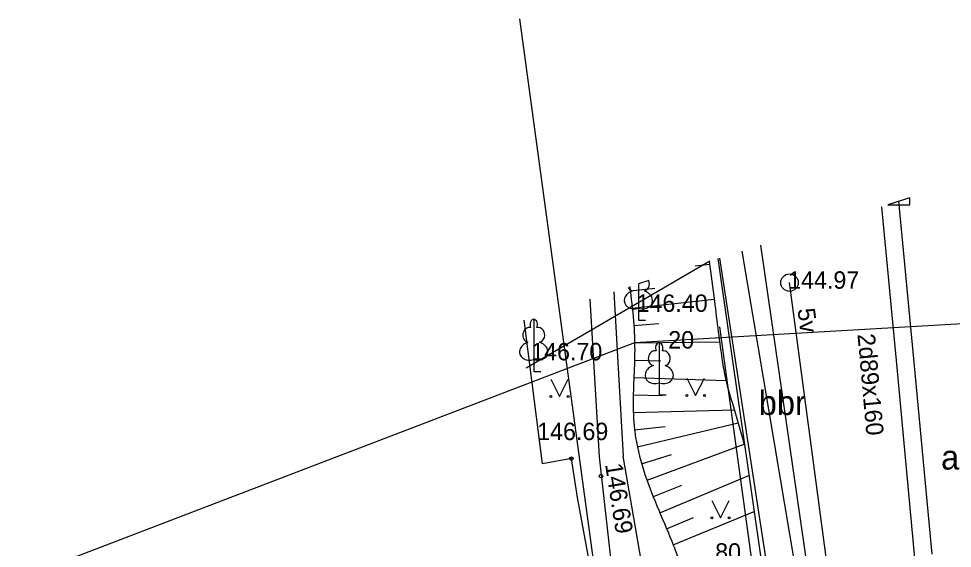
# Model space of a CAD drawing. Extents: x 728492 to 729038, y 272968 to 273171.
# Drawn here: x 728641.64 to 728668.45, y 273088.71 to 273103.92 of the extents above; entities that cross this region are included whole.
import ezdxf

# ---------------------------------------------------------------- set-up
doc = ezdxf.new("R2010")
doc.units = 0
for name, color, linetype in [('APGR_SARK_####_####_#', 7, 'Continuous'), ('BUVE_EKAS_####_####_#', 7, 'Continuous'), ('CELI_CMAL_####_####_#', 7, 'Continuous'), ('CELI_CSEG_####_TKST_#', 7, 'Continuous'), ('ELEK_ELEM_####_####_#', 7, 'Continuous'), ('ELEK_VADV_ZSPR_####_#', 7, 'Continuous'), ('ELEK_VADV_ZSPR_TKST_#', 7, 'Continuous'), ('Level 18', 7, 'Continuous'), ('NORB_ZOGS_SBST_####_#', 7, 'Continuous'), ('RAMI_UZMR_####_####_#', 7, 'Continuous'), ('RELJ_AATZ_####_TKST_#', 7, 'Continuous'), ('RELJ_ELEM_####_####_#', 7, 'Continuous'), ('RELJ_NOGA_####_####_#', 7, 'Continuous'), ('RELJ_NOGL_####_####_#', 7, 'Continuous'), ('ROBZ_UZMR_####_####_#', 7, 'Continuous'), ('SAKK_KKAN_####_####_#', 7, 'Continuous'), ('SAKT_VADV_PKAB_####_#', 7, 'Continuous'), ('SILT_VADP_UDEN_####_#', 7, 'Continuous'), ('SILT_VADP_UDEN_TKAM_#', 7, 'Continuous'), ('SILT_VADP_UDEN_TKST_#', 7, 'Continuous'), ('TERT_DIAM_####_TKST_#', 7, 'Continuous'), ('TERT_ELEM_####_####_#', 7, 'Continuous')]:
    doc.layers.add(name, color=color, linetype=linetype)

msp = doc.modelspace()

# ---------------------------------------------------------------- linework, layer by layer
at = {"layer": 'APGR_SARK_####_####_#'}
msp.add_lwpolyline([(728659.143, 273080.982), (728656.032, 273103.923)], dxfattribs=at)
at = {"layer": 'BUVE_EKAS_####_####_#'}
for p, q in [((728657.508, 273091.288), (728656.678, 273091.136)), ((728657.68, 273090.168), (728657.508, 273091.288)), ((728658.403, 273086.287), (728657.68, 273090.168))]:
    msp.add_line(p, q, dxfattribs=at)
at = {"layer": 'CELI_CMAL_####_####_#'}
for p, q in [((728664.35, 273087.706), (728662.947, 273097.421)), ((728658.724, 273096.082), (728658.999, 273091.36)), ((728658.04, 273095.865), (728658.304, 273091.34)), ((728658.304, 273091.34), (728658.856, 273086.395)), ((728659.806, 273086.622), (728658.999, 273091.36))]:
    msp.add_line(p, q, dxfattribs=at)
msp.add_lwpolyline([(728663.412, 273086.324), (728661.767, 273097.047)], dxfattribs=at)
at = {"layer": 'ELEK_ELEM_####_####_#'}
msp.add_circle((728663.771, 273096.342), 0.25, dxfattribs=at)
at = {"layer": 'ELEK_VADV_ZSPR_####_#'}
msp.add_line((728666.081, 273078.979), (728663.771, 273096.342), dxfattribs=at)
at = {"layer": 'Level 18'}
msp.add_line((728661.717, 273097.031), (728663.093, 273087.406), dxfattribs=at)
at = {"layer": 'NORB_ZOGS_SBST_####_#'}
msp.add_line((728656.678, 273091.136), (728656.153, 273095.267), dxfattribs=at)
at = {"layer": 'RAMI_UZMR_####_####_#'}
msp.add_lwpolyline([(728726.814, 273102.175), (728686.914, 273096.216), (728659.323, 273094.615), (728619.629, 273079.414), (728545.121, 273067.256)], dxfattribs=at)
at = {"layer": 'RELJ_ELEM_####_####_#'}
for centre in [(728657.508, 273091.288), (728658.359, 273090.788)]:
    msp.add_circle(centre, 0.05, dxfattribs=at)
at = {"layer": 'RELJ_NOGA_####_####_#'}
for p, q in [((728661.061, 273096.823), (728661.479, 273096.87)), ((728659.196, 273096.109), (728659.9, 273096.187)), ((728659.25, 273095.612), (728661.609, 273095.865)), ((728659.299, 273095.114), (728660.015, 273095.165)), ((728659.323, 273094.615), (728661.77, 273094.637)), ((728659.316, 273094.115), (728660.076, 273094.092)), ((728659.3, 273093.615), (728661.948, 273093.528)), ((728659.288, 273093.115), (728660.123, 273093.105)), ((728659.286, 273092.615), (728662.187, 273092.69)), ((728659.402, 273091.624), (728662.298, 273092.318)), ((728659.321, 273092.117), (728660.205, 273092.21)), ((728659.684, 273090.665), (728662.465, 273091.7)), ((728659.525, 273091.139), (728660.38, 273091.409)), ((728660.047, 273089.734), (728662.607, 273090.801)), ((728659.861, 273090.198), (728660.675, 273090.521)), ((728660.43, 273088.81), (728662.754, 273089.771)), ((728660.239, 273089.272), (728661.013, 273089.592))]:
    msp.add_line(p, q, dxfattribs=at)
msp.add_spline([(728659.183, 273096.227), (728659.291, 273095.231), (728659.325, 273094.399), (728659.298, 273093.563), (728659.283, 273092.727), (728659.302, 273092.311), (728659.322, 273092.104), (728659.351, 273091.897), (728659.621, 273090.834), (728660.016, 273089.807), (728660.44, 273088.787), (728660.632, 273088.27), (728660.796, 273087.745), (728661.008, 273086.925), (728661.012, 273086.909)], degree=3, dxfattribs=at)
at = {"layer": 'RELJ_NOGL_####_####_#'}
msp.add_spline([(728661.468, 273096.952), (728661.616, 273095.812), (728661.848, 273094.052), (728661.952, 273093.509), (728662.1, 273092.974), (728662.262, 273092.442), (728662.412, 273091.908), (728662.495, 273091.585)], degree=3, dxfattribs=at)
at = {"layer": 'ROBZ_UZMR_####_####_#'}
msp.add_line((728664.052, 273078.4), (728661.768, 273095.074), dxfattribs=at)
at = {"layer": 'SAKK_KKAN_####_####_#'}
msp.add_lwpolyline([(728662.399, 273097.247), (728664.534, 273084.574)], dxfattribs=at)
at = {"layer": 'SAKT_VADV_PKAB_####_#'}
msp.add_line((728661.482, 273096.956), (728656.205, 273093.887), dxfattribs=at)
at = {"layer": 'SILT_VADP_UDEN_####_#'}
for p, q in [((728666.865, 273093.904), (728666.424, 273098.523)), ((728667.363, 273093.952), (728666.911, 273098.678))]:
    msp.add_line(p, q, dxfattribs=at)
for points in [[(728667.373, 273088.428), (728666.865, 273093.904)], [(728667.865, 273088.545), (728667.363, 273093.95)]]:
    msp.add_lwpolyline(points, dxfattribs=at)
at = {"layer": 'SILT_VADP_UDEN_TKAM_#'}
msp.add_line((728667.228, 273098.778), (728666.597, 273098.578), dxfattribs=at)
msp.add_lwpolyline([(728666.597, 273098.578), (728667.228, 273098.578), (728667.228, 273098.778)], dxfattribs=at)
at = {"layer": 'TERT_ELEM_####_####_#'}
for p, q in [((728659.73, 273096.401), (728659.433, 273096.307)), ((728659.433, 273096.307), (728659.433, 273095.609)), ((728659.433, 273095.609), (728659.433, 273095.262)), ((728659.433, 273095.262), (728659.633, 273095.262)), ((728656.427, 273094.135), (728656.427, 273093.788)), ((728656.427, 273093.788), (728656.627, 273093.788)), ((728656.916, 273093.574), (728657.166, 273093.074)), ((728657.166, 273093.074), (728657.416, 273093.574)), ((728660.029, 273093.462), (728660.029, 273093.115)), ((728660.826, 273093.602), (728661.076, 273093.102)), ((728661.076, 273093.102), (728661.326, 273093.602)), ((728660.029, 273093.115), (728660.229, 273093.115)), ((728661.54, 273090.088), (728661.79, 273089.588)), ((728661.79, 273089.588), (728662.04, 273090.088))]:
    msp.add_line(p, q, dxfattribs=at)
for points in [[(728656.427, 273095.288), (728656.427, 273094.135)], [(728656.517, 273095.056), (728656.516, 273095.057)], [(728660.029, 273094.615), (728660.029, 273093.462)], [(728660.119, 273094.383), (728660.118, 273094.384)]]:
    msp.add_lwpolyline(points, dxfattribs=at)
for centre, radius in [((728656.916, 273093.073), 0.028), ((728657.416, 273093.073), 0.0263), ((728660.826, 273093.102), 0.028), ((728661.326, 273093.102), 0.0263), ((728661.54, 273089.588), 0.028), ((728662.04, 273089.588), 0.0263)]:
    msp.add_circle(centre, radius, dxfattribs=at)
for centre, major_axis, ratio, start_param, end_param in [((728659.561, 273096.317), (0.039, -0.212), 0.861323, 0, 1.813048), ((728659.343, 273095.855), (0.307, 0.095), 0.814445, 1.570796, 4.752015), ((728659.305, 273096.317), (-0.039, -0.212), 0.861323, 5.376383, 6.283185), ((728659.523, 273095.855), (-0.307, 0.095), 0.814445, 1.531171, 4.712389), ((728656.427, 273095.138), (0, -0.15), 0.707107, 3.14537, 5.287485), ((728656.427, 273095.138), (0, -0.15), 0.707107, 0.995701, 3.137816), ((728656.299, 273094.843), (-0.039, -0.212), 0.861323, 3.141593, 6.283185), ((728656.555, 273094.843), (0.039, -0.212), 0.861323, 0, 3.141593), ((728656.337, 273094.381), (0.307, 0.095), 0.814445, 1.570796, 4.752015), ((728656.517, 273094.381), (-0.307, 0.095), 0.814445, 1.531171, 4.712389), ((728660.029, 273094.465), (0, -0.15), 0.707107, 3.14537, 5.287485), ((728660.029, 273094.465), (0, -0.15), 0.707107, 0.995701, 3.137816), ((728659.901, 273094.17), (-0.039, -0.212), 0.861323, 3.141593, 6.283185), ((728660.157, 273094.17), (0.039, -0.212), 0.861323, 0, 3.141593), ((728659.939, 273093.708), (0.307, 0.095), 0.814445, 1.570796, 4.752015), ((728660.119, 273093.708), (-0.307, 0.095), 0.814445, 1.531171, 4.712389)]:
    msp.add_ellipse(centre, major_axis=major_axis, ratio=ratio, start_param=start_param, end_param=end_param, dxfattribs=at)

# ---------------------------------------------------------------- texts
at = {"layer": 'CELI_CSEG_####_TKST_#'}
for s, p in [('bbr', (728662.887, 273092.541)), ('a', (728668.123, 273090.974))]:
    msp.add_text(s, height=0.7, dxfattribs=at).set_placement(p)
at = {"layer": 'ELEK_VADV_ZSPR_TKST_#'}
msp.add_text('5v', height=0.5, rotation=277.242, dxfattribs=at).set_placement((728663.998, 273095.58))
at = {"layer": 'RELJ_AATZ_####_TKST_#'}
for s, p in [(' 144.97', (728663.544, 273096.167)), (' 146.40', (728659.19, 273095.503)), (' 146.70', (728656.165, 273094.11)), (' 146.69', (728656.337, 273091.819))]:
    msp.add_text(s, height=0.5, dxfattribs=at).set_placement(p)
msp.add_text(' 146.69', height=0.5, rotation=278.8575, dxfattribs=at).set_placement((728658.446, 273091.304))
at = {"layer": 'SILT_VADP_UDEN_TKST_#'}
msp.add_text('2d89x160', height=0.5, rotation=275.0962, dxfattribs=at).set_placement((728665.722, 273094.858))
at = {"layer": 'TERT_DIAM_####_TKST_#'}
for s, p in [('20', (728660.288, 273094.45)), ('80', (728661.636, 273088.356))]:
    msp.add_text(s, height=0.5, dxfattribs=at).set_placement(p)

doc.saveas('drawing.dxf')
